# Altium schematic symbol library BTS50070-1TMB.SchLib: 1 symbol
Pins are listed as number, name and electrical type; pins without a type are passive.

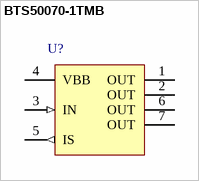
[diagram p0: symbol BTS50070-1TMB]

## BTS50070-1TMB
designator U?
Smart High-Side Power Switch PROFET, 1 Channel, 12 A Load Current, -40 to 150 degC, PG-TO220-7-12, Tube, Green; Manufacturer: Infineon; PartNumber: BTS50070-1TMB; Channels: 1; Green: TRUE; Group: Automotive Qualified; Load Current (typ): 12 A; Ptot (max): 81 W; Recommended Operating Voltage Max.: 30 V; Recommended Operating Voltage Min.: 5.5 V; RON @ 25degreesC: 7 mOhm; RON(max) @ 150degreesC: 14 mOhm; toff (max): 600 us; ton (max): 550 us
footprint INF-PG-TO220-7-12 (FM, 7-Leads, Body 10x4.4mm, Pitch 1.27mm)
pins: 1 OUT (power) "Output; output to the load; pin 1, 2, 6 and 7 must be externally shorted.1", 2 OUT (power) "Output; output to the load; pin 1, 2, 6 and 7 must be externally shorted.1", 3 IN (in) "Input; activates the power switch if shorted to ground", 4 VBB (power) "Supply Voltage; positive power supply voltage; tab and pin 4 are internally shorted.", 5 IS (out) "Sense Output; Diagnostic feedback; provides at normal operation a sense current  proportional to the load current; in case of overload, overtemperature and/or short  circuit a defined current is provided", 6 OUT (power) "Output; output to the load; pin 1, 2, 6 and 7 must be externally shorted.1", 7 OUT (power) "Output; output to the load; pin 1, 2, 6 and 7 must be externally shorted.1"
